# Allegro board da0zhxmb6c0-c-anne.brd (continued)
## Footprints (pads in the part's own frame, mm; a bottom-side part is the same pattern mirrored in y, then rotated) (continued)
BGA1170-INTEL-BRASWELL
  round 0.47 smd: A3(-11.814,-11.951) A52(-11.814,12.383) B2(-11.383,-12.383) B53(-11.383,12.814) BH1(11.383,-12.814) BH53(11.383,12.814) BJ2(11.814,-12.383) BJ52(11.814,12.383) C1(-10.951,-12.814)
  round 0.356 smd: A5(-11.814,-11.17) A6(-11.814,-10.447) A7(-11.814,-9.748) A9(-11.814,-8.836) A47(-11.814,9.621) A48(-11.814,10.294) A49(-11.814,10.992) A51(-11.814,11.773) B4(-11.238,-11.632) B5(-11.222,-11.038) B6(-11.221,-10.445) B8(-11.224,-9.258) B46(-11.224,9.258) B48(-11.221,10.445) B49(-11.222,11.038) B50(-11.238,11.632) B52(-11.225,12.225) BC1(8.621,-12.814) BC2(8.852,-12.246) BC52(8.852,12.246) BC53(8.621,12.814) BD1(9.294,-12.814) BD2(9.445,-12.221) BD52(9.445,12.221) BD53(9.294,12.814) BE1(9.992,-12.814) BE2(10.038,-12.222) BE52(10.038,12.222) BE53(9.992,12.814) BF2(10.632,-12.238) BF52(10.632,12.238) BG1(10.773,-12.814) BG3(10.644,-11.644) BG51(10.644,11.644) BG53(10.773,12.814) BH2(11.225,-12.225) BH4(11.238,-11.632) BH5(11.222,-11.038) BH6(11.221,-10.445) BH8(11.224,-9.258) BH46(11.224,9.258) BH48(11.221,10.445) BH49(11.222,11.038) BH50(11.238,11.632) BH52(11.225,12.225) BJ3(11.814,-11.773) BJ5(11.814,-10.992) BJ6(11.814,-10.294) BJ7(11.814,-9.621) BJ47(11.814,9.621) BJ48(11.814,10.294) BJ49(11.814,10.992) BJ51(11.814,11.773) C3(-10.644,-11.644) C51(-10.644,11.644) C53(-10.773,12.814) D2(-10.632,-12.238) D52(-10.632,12.238) E1(-10.17,-12.814) E2(-10.038,-12.222) E52(-10.038,12.222) E53(-9.992,12.814) F1(-9.447,-12.814) F2(-9.445,-12.221) F52(-9.445,12.221) F53(-9.294,12.814) G1(-8.679,-12.814) G2(-8.852,-12.246) G52(-8.852,12.246) G53(-8.621,12.814) J1(-7.816,-12.814)
  oval 0.343x0.254 smd: A11(-11.814,-7.774) A13(-11.814,-6.803) A15(-11.814,-5.831) A17(-11.814,-4.859) A19(-11.814,-3.887) A21(-11.814,-2.915) A23(-11.814,-1.944) A25(-11.814,-0.972) A27(-11.814,0) A29(-11.814,0.972) A31(-11.814,1.944) A33(-11.814,2.915) A35(-11.814,3.887) A37(-11.814,4.859) A39(-11.814,5.831) A41(-11.814,6.803) A43(-11.814,7.774) A45(-11.814,8.746) BJ9(11.814,-8.746) BJ11(11.814,-7.774) BJ13(11.814,-6.803) BJ15(11.814,-5.831) BJ17(11.814,-4.859) BJ19(11.814,-3.887) BJ21(11.814,-2.915) BJ23(11.814,-1.944) BJ25(11.814,-0.972) BJ27(11.814,0) BJ29(11.814,0.972) BJ31(11.814,1.944) BJ33(11.814,2.915) BJ35(11.814,3.887) BJ37(11.814,4.859) BJ39(11.814,5.831) BJ41(11.814,6.803) BJ43(11.814,7.774) BJ45(11.814,8.746)
  custom 0.064x0.064 smd: AA1(-1.944,-12.814) AA53(-1.944,12.814) AC1(-0.972,-12.814) AC53(-0.972,12.814) AE1(0,-12.814) AE53(0,12.814) AG1(0.972,-12.814) AG53(0.972,12.814) AJ1(1.944,-12.814) AJ53(1.944,12.814) AL1(2.915,-12.814) AL53(2.915,12.814) AN1(3.887,-12.814) AN53(3.887,12.814) AR1(4.859,-12.814) AR53(4.859,12.814) AU1(5.831,-12.814) AU53(5.831,12.814) AW1(6.803,-12.814) AW53(6.803,12.814) BA1(7.774,-12.814) BA53(7.774,12.814) J53(-7.774,12.814) L1(-6.803,-12.814) L53(-6.802,12.814) N1(-5.831,-12.814) N53(-5.831,12.814) R1(-4.859,-12.814) R53(-4.859,12.814) U1(-3.887,-12.814) U53(-3.887,12.814) W1(-2.915,-12.814) W53(-2.915,12.814)
  round 0.279 smd: AA3(-1.944,-12.071) AA51(-1.944,12.071) AB2(-1.458,-12.429) AB3(-1.458,-11.73) AB51(-1.458,11.73) AB52(-1.458,12.429) AC3(-0.972,-12.071) AC51(-0.972,12.071) AD2(-0.486,-12.429) AD3(-0.48,-11.715) AD51(-0.48,11.715) AD52(-0.486,12.429) AE3(0,-12.071) AE4(0,-11.366) AE50(0,11.366) AE51(0,12.071) AF2(0.486,-12.429) AF3(0.48,-11.715) AF51(0.48,11.715) AF52(0.486,12.429) AG3(0.972,-12.071) AG51(0.972,12.071) AH2(1.458,-12.429) AH3(1.458,-11.73) AH51(1.458,11.73) AH52(1.458,12.429) AJ3(1.944,-12.071) AJ51(1.944,12.071) AK2(2.43,-12.429) AK3(2.43,-11.73) AK51(2.43,11.73) AK52(2.43,12.429) AL3(2.915,-12.071) AL51(2.915,12.071) AM2(3.401,-12.429) AM3(3.401,-11.73) AM51(3.401,11.73) AM52(3.401,12.429) AN3(3.887,-12.071) AN51(3.887,12.071) AP2(4.373,-12.429) AP3(4.373,-11.73) AP51(4.373,11.73) AP52(4.373,12.429) AR3(4.859,-12.071) AR51(4.859,12.071) AT2(5.345,-12.429) AT3(5.345,-11.73) AT51(5.345,11.73) AT52(5.345,12.429) AU3(5.831,-12.071) AU51(5.831,12.071) AV2(6.317,-12.429) AV3(6.317,-11.73) AV51(6.317,11.73) AV52(6.317,12.429) AW3(6.803,-12.071) AW51(6.803,12.071) AY2(7.289,-12.429) AY3(7.289,-11.73) AY51(7.289,11.73) AY52(7.289,12.429) B10(-11.429,-8.26) B12(-11.429,-7.289) B14(-11.429,-6.317) B16(-11.429,-5.345) B18(-11.429,-4.373) B20(-11.429,-3.401) B22(-11.429,-2.43) B24(-11.429,-1.458) B26(-11.429,-0.486) B28(-11.429,0.486) B30(-11.429,1.458) B32(-11.429,2.43) B34(-11.429,3.401) B36(-11.429,4.373) B38(-11.429,5.345) B40(-11.429,6.317) B42(-11.429,7.289) B44(-11.429,8.26) BA3(7.774,-12.071) BA51(7.774,12.071) BB3(8.351,-11.929) BB51(8.351,11.929) BF27(10.366,0) BG9(11.028,-8.698) BG11(11.071,-7.774) BG12(10.73,-7.289) BG13(11.071,-6.803) BG14(10.73,-6.317) BG15(11.071,-5.831) BG16(10.73,-5.345) BG17(11.071,-4.859) BG18(10.73,-4.373) BG19(11.071,-3.887) BG20(10.73,-3.401) BG21(11.071,-2.915) BG22(10.73,-2.43) BG23(11.071,-1.944) BG24(10.73,-1.458) BG25(11.071,-0.972) BG26(10.715,-0.48) BG27(11.071,0) BG28(10.715,0.48) BG29(11.071,0.972) BG30(10.73,1.458) BG31(11.071,1.944) BG32(10.73,2.43) BG33(11.071,2.915) BG34(10.73,3.401) BG35(11.071,3.887) BG36(10.73,4.373) BG37(11.071,4.859) BG38(10.73,5.345) BG39(11.071,5.831) BG40(10.73,6.317) BG41(11.071,6.803) BG42(10.73,7.289) BG43(11.071,7.774) BG45(11.028,8.698) BH10(11.429,-8.26) BH12(11.429,-7.289) BH14(11.429,-6.317) BH16(11.429,-5.345) BH18(11.429,-4.373) BH20(11.429,-3.401) BH22(11.429,-2.43) BH24(11.429,-1.458) BH26(11.429,-0.486) BH28(11.429,0.486) BH30(11.429,1.458) BH32(11.429,2.43) BH34(11.429,3.401) BH36(11.429,4.373) BH38(11.429,5.345) BH40(11.429,6.317) BH42(11.429,7.289) BH44(11.429,8.26) C9(-11.028,-8.698) C11(-11.071,-7.774) C12(-10.73,-7.289) C13(-11.071,-6.803) C14(-10.73,-6.317) C15(-11.071,-5.831) C16(-10.73,-5.345) C17(-11.071,-4.859) C18(-10.73,-4.373) C19(-11.071,-3.887) C20(-10.73,-3.401) C21(-11.071,-2.915) C22(-10.73,-2.43) C23(-11.071,-1.944) C24(-10.73,-1.458) C25(-11.071,-0.972) C26(-10.715,-0.48) C27(-11.071,0) C28(-10.715,0.48) C29(-11.071,0.972) C30(-10.73,1.458) C31(-11.071,1.944) C32(-10.73,2.43) C33(-11.071,2.915) C34(-10.73,3.401) C35(-11.071,3.887) C36(-10.73,4.373) C37(-11.071,4.859) C38(-10.73,5.345) C39(-11.071,5.831) C40(-10.73,6.317) C41(-11.071,6.803) C42(-10.73,7.289) C43(-11.071,7.774) C45(-11.028,8.698) D27(-10.366,0) H3(-8.351,-11.929) H51(-8.351,11.929) J3(-7.774,-12.071) J51(-7.774,12.071) K2(-7.289,-12.429) K3(-7.289,-11.73) K51(-7.289,11.73) K52(-7.289,12.429) L3(-6.803,-12.071) L51(-6.803,12.071) M2(-6.317,-12.429) M3(-6.317,-11.73) M51(-6.317,11.73) M52(-6.317,12.429) N3(-5.831,-12.071) N51(-5.831,12.071) P2(-5.345,-12.429) P3(-5.345,-11.73) P51(-5.345,11.73) P52(-5.345,12.429) R3(-4.859,-12.071) R51(-4.859,12.071) T2(-4.373,-12.429) T3(-4.373,-11.73) T51(-4.373,11.73) T52(-4.373,12.429) U3(-3.887,-12.071) U51(-3.887,12.071) V2(-3.401,-12.429) V3(-3.401,-11.73) V51(-3.401,11.73) V52(-3.401,12.429) W3(-2.915,-12.071) W51(-2.915,12.071) Y2(-2.43,-12.429) Y3(-2.43,-11.73) Y51(-2.43,11.73) Y52(-2.43,12.429)
  round 0.33 smd: AA16(-1.961,-5.307) AA18(-1.961,-4.549) AA19(-1.961,-3.791) AA21(-1.961,-3.033) AA22(-1.961,-2.275) AA24(-1.961,-1.516) AA25(-1.961,-0.758) AA27(-1.961,0) AA29(-1.961,0.758) AA30(-1.961,1.516) AA32(-1.961,2.275) AA33(-1.961,3.033) AA35(-1.961,3.791) AA36(-1.961,4.549) AA38(-1.961,5.307) AC16(-1.177,-5.307) AC18(-1.177,-4.549) AC19(-1.177,-3.791) AC21(-1.177,-3.033) AC22(-1.177,-2.275) AC24(-1.177,-1.516) AC25(-1.177,-0.758) AC27(-1.177,0) AC29(-1.177,0.758) AC30(-1.177,1.516) AC32(-1.177,2.275) AC33(-1.177,3.033) AC35(-1.177,3.791) AC36(-1.177,4.549) AC38(-1.177,5.307) AD16(-0.392,-5.307) AD18(-0.392,-4.549) AD19(-0.392,-3.791) AD21(-0.392,-3.033) AD22(-0.392,-2.275) AD24(-0.392,-1.516) AD25(-0.392,-0.758) AD27(-0.392,0) AD29(-0.392,0.758) AD30(-0.392,1.516) AD32(-0.392,2.275) AD33(-0.392,3.033) AD35(-0.392,3.791) AD36(-0.392,4.549) AD38(-0.392,5.307) AF16(0.392,-5.307) AF18(0.392,-4.549) AF19(0.392,-3.791) AF21(0.392,-3.033) AF22(0.392,-2.275) AF24(0.392,-1.516) AF25(0.392,-0.758) AF27(0.392,0) AF29(0.392,0.758) AF30(0.392,1.516) AF32(0.392,2.275) AF33(0.392,3.033) AF35(0.392,3.791) AF36(0.392,4.549) AF38(0.392,5.307) AG16(1.177,-5.307) AG18(1.177,-4.549) AG19(1.177,-3.791) AG21(1.177,-3.033) AG22(1.177,-2.275) AG24(1.177,-1.516) AG25(1.177,-0.758) AG27(1.177,0) AG29(1.177,0.758) AG30(1.177,1.516) AG32(1.177,2.275) AG33(1.177,3.033) AG35(1.177,3.791) AG36(1.177,4.549) AG38(1.177,5.307) AJ16(1.961,-5.307) AJ18(1.961,-4.549) AJ19(1.961,-3.791) AJ21(1.961,-3.033) AJ22(1.961,-2.275) AJ24(1.961,-1.516) AJ25(1.961,-0.758) AJ27(1.961,0) AJ29(1.961,0.758) AJ30(1.961,1.516) AJ32(1.961,2.275) AJ33(1.961,3.033) AJ35(1.961,3.791) AJ36(1.961,4.549) AJ38(1.961,5.307) AK16(2.745,-5.307) AK18(2.745,-4.549) AK19(2.745,-3.791) AK21(2.745,-3.033) AK22(2.745,-2.275) AK24(2.745,-1.516) AK25(2.745,-0.758) AK27(2.745,0) AK29(2.745,0.758) AK30(2.745,1.516) AK32(2.745,2.275) AK33(2.745,3.033) AK35(2.745,3.791) AK36(2.745,4.549) AK38(2.745,5.307) AM16(3.53,-5.307) AM18(3.53,-4.549) AM19(3.53,-3.791) AM21(3.53,-3.033) AM22(3.53,-2.275) AM24(3.53,-1.516) AM25(3.53,-0.758) AM27(3.53,0) AM29(3.53,0.758) AM30(3.53,1.516) AM32(3.53,2.275) AM33(3.53,3.033) AM35(3.53,3.791) AM36(3.53,4.549) AM38(3.53,5.307) AN16(4.314,-5.307) AN18(4.314,-4.549) AN19(4.314,-3.791) AN21(4.314,-3.033) AN22(4.314,-2.275) AN24(4.314,-1.516) AN25(4.314,-0.758) AN27(4.314,0) AN29(4.314,0.758) AN30(4.314,1.516) AN32(4.314,2.275) AN33(4.314,3.033) AN35(4.314,3.791) AN36(4.314,4.549) AN38(4.314,5.307) U16(-4.314,-5.307) U18(-4.314,-4.549) U19(-4.314,-3.791) U21(-4.314,-3.033) U22(-4.314,-2.275) U24(-4.314,-1.516) U25(-4.314,-0.758) U27(-4.314,0) U29(-4.314,0.758) U30(-4.314,1.516) U32(-4.314,2.275) U33(-4.314,3.033) U35(-4.314,3.791) U36(-4.314,4.549) U38(-4.314,5.307) V16(-3.53,-5.307) V18(-3.53,-4.549) V19(-3.53,-3.791) V21(-3.53,-3.033) V22(-3.53,-2.275) V24(-3.53,-1.516) V25(-3.53,-0.758) V27(-3.53,0) V29(-3.53,0.758) V30(-3.53,1.516) V32(-3.53,2.275) V33(-3.53,3.033) V35(-3.53,3.791) V36(-3.53,4.549) V38(-3.53,5.307) Y16(-2.745,-5.307) Y18(-2.745,-4.549) Y19(-2.745,-3.791) Y21(-2.745,-3.033) Y22(-2.745,-2.275) Y24(-2.745,-1.516) Y25(-2.745,-0.758) Y27(-2.745,0) Y29(-2.745,0.758) Y30(-2.745,1.516) Y32(-2.745,2.275) Y33(-2.745,3.033) Y35(-2.745,3.791) Y36(-2.745,4.549) Y38(-2.745,5.307)
  round 0.305 smd: AB4(-1.448,-11.137) AB6(-1.448,-10.463) AB7(-1.448,-9.752) AB9(-1.448,-9.041) AB10(-1.448,-8.33) AB12(-1.448,-7.618) AB13(-1.448,-6.907) AB14(-1.448,-6.196) AB40(-1.448,6.196) AB41(-1.448,6.907) AB42(-1.448,7.618) AB44(-1.448,8.33) AB45(-1.448,9.041) AB47(-1.448,9.752) AB48(-1.448,10.463) AB50(-1.448,11.137) AD4(-0.463,-10.995) AD6(-0.525,-10.404) AD7(-0.475,-9.752) AD9(-0.475,-9.041) AD10(-0.475,-8.33) AD12(-0.475,-7.618) AD13(-0.475,-6.907) AD14(-0.475,-6.196) AD40(-0.475,6.196) AD41(-0.475,6.907) AD42(-0.475,7.618) AD44(-0.475,8.33) AD45(-0.475,9.041) AD47(-0.475,9.752) AD48(-0.525,10.404) AD50(-0.463,10.995) AE6(0,-10.108) AE8(0,-9.396) AE9(0,-8.685) AE11(0,-7.974) AE12(0,-7.263) AE14(0,-6.552) AE40(0,6.552) AE42(0,7.263) AE43(0,7.974) AE45(0,8.685) AE46(0,9.396) AE48(0,10.108) AF4(0.463,-10.995) AF6(0.525,-10.404) AF7(0.475,-9.752) AF9(0.475,-9.041) AF10(0.475,-8.33) AF12(0.475,-7.618) AF13(0.475,-6.907) AF14(0.475,-6.196) AF40(0.475,6.196) AF41(0.475,6.907) AF42(0.475,7.618) AF44(0.475,8.33) AF45(0.475,9.041) AF47(0.475,9.752) AF48(0.525,10.404) AF50(0.463,10.995) AH4(1.448,-11.137) AH6(1.448,-10.463) AH7(1.448,-9.752) AH9(1.448,-9.041) AH10(1.448,-8.33) AH12(1.448,-7.618) AH13(1.448,-6.907) AH14(1.448,-6.196) AH40(1.448,6.196) AH41(1.448,6.907) AH42(1.448,7.618) AH44(1.448,8.33) AH45(1.448,9.041) AH47(1.448,9.752) AH48(1.448,10.463) AH50(1.448,11.137) AK4(2.439,-11.137) AK6(2.439,-10.463) AK7(2.439,-9.752) AK9(2.439,-9.041) AK10(2.439,-8.33) AK12(2.439,-7.618) AK13(2.439,-6.907) AK14(2.439,-6.196) AK40(2.439,6.196) AK41(2.439,6.907) AK42(2.439,7.618) AK44(2.439,8.33) AK45(2.439,9.041) AK47(2.439,9.752) AK48(2.439,10.463) AK50(2.439,11.137) AM4(3.386,-11.137) AM6(3.412,-10.463) AM7(3.412,-9.752) AM9(3.412,-9.041) AM10(3.412,-8.33) AM12(3.412,-7.618) AM13(3.412,-6.907) AM14(3.412,-6.196) AM40(3.412,6.196) AM41(3.412,6.907) AM42(3.412,7.618) AM44(3.412,8.33) AM45(3.412,9.041) AM47(3.412,9.752) AM48(3.412,10.463) AM50(3.386,11.137) AN5(3.887,-10.819) AN6(3.887,-10.108) AN8(3.887,-9.396) AN9(3.887,-8.685) AN11(3.887,-7.974) AN12(3.887,-7.263) AN14(3.887,-6.552) AN40(3.887,6.552) AN42(3.887,7.263) AN43(3.887,7.974) AN45(3.887,8.685) AN46(3.887,9.396) AN48(3.887,10.108) AN49(3.887,10.819) AP4(4.388,-11.137) AP6(4.362,-10.463) AP7(4.362,-9.752) AP9(4.362,-9.041) AP10(4.362,-8.33) AP12(4.362,-7.618) AP13(4.362,-6.907) AP14(4.362,-6.196) AP40(4.362,6.196) AP41(4.362,6.907) AP42(4.362,7.618) AP44(4.362,8.33) AP45(4.362,9.041) AP47(4.362,9.752) AP48(4.362,10.463) AP50(4.388,11.137) AT4(5.336,-11.137) AT6(5.336,-10.463) AT7(5.336,-9.752) AT9(5.336,-9.041) AT10(5.336,-8.33) AT12(5.336,-7.618) AT13(5.336,-6.907) AT14(5.336,-6.305) AT16(5.196,-5.336) AT18(5.196,-4.362) AT19(5.552,-3.887) AT20(5.196,-3.412) AT22(5.196,-2.439) AT24(5.196,-1.448) AT26(5.196,-0.475) AT27(5.552,0) AT28(5.196,0.475) AT30(5.196,1.448) AT32(5.196,2.439) AT34(5.196,3.412) AT35(5.552,3.887) AT36(5.196,4.362) AT38(5.196,5.336) AT40(5.336,6.305) AT41(5.336,6.907) AT42(5.336,7.618) AT44(5.336,8.33) AT45(5.336,9.041) AT47(5.336,9.752) AT48(5.336,10.463) AT50(5.336,11.137) AU16(5.907,-5.336) AU18(5.907,-4.362) AU20(5.907,-3.412) AU22(5.907,-2.439) AU24(5.907,-1.448) AU26(5.907,-0.475) AU28(5.907,0.475) AU30(5.907,1.448) AU32(5.907,2.439) AU34(5.907,3.412) AU36(5.907,4.362) AU38(5.907,5.336) AV4(6.326,-11.137) AV6(6.326,-10.463) AV7(6.326,-9.752) AV9(6.326,-9.041) AV10(6.326,-8.33) AV12(6.326,-7.618) AV13(6.326,-6.907) AV14(6.446,-6.326) AV16(6.618,-5.336) AV18(6.618,-4.362) AV19(6.263,-3.887) AV20(6.618,-3.412) AV22(6.618,-2.439) AV24(6.618,-1.448) AV26(6.618,-0.475) AV27(6.263,0) AV28(6.618,0.475) AV30(6.618,1.448) AV32(6.618,2.439) AV34(6.618,3.412) AV35(6.263,3.887) AV36(6.618,4.362) AV38(6.618,5.336) AV40(6.446,6.326) AV41(6.326,6.907) AV42(6.326,7.618) AV44(6.326,8.33) AV45(6.326,9.041) AV47(6.326,9.752) AV48(6.326,10.463) AV50(6.326,11.137) AW13(6.915,-6.751) AW19(6.974,-3.887) AW27(6.974,0) AW35(6.974,3.887) AW41(6.915,6.751) AY4(7.317,-11.137) AY6(7.317,-10.463) AY7(7.317,-9.752) AY9(7.317,-9.041) AY10(7.317,-8.33) AY12(7.34,-7.317) AY14(7.33,-6.326) AY16(7.33,-5.336) AY18(7.33,-4.362) AY20(7.33,-3.412) AY22(7.33,-2.439) AY24(7.33,-1.448) AY26(7.33,-0.475) AY28(7.33,0.475) AY30(7.33,1.448) AY32(7.33,2.439) AY34(7.33,3.412) AY36(7.33,4.362) AY38(7.33,5.336) AY40(7.33,6.326) AY42(7.34,7.317) AY44(7.317,8.33) AY45(7.317,9.041) AY47(7.317,9.752) AY48(7.317,10.463) AY50(7.317,11.137) B7(-11.23,-9.852) B47(-11.23,9.852) BA12(8.041,-7.317) BA14(8.041,-6.326) BA16(8.041,-5.336) BA18(8.041,-4.362) BA19(7.685,-3.887) BA20(8.041,-3.412) BA22(8.041,-2.439) BA24(8.041,-1.448) BA26(8.041,-0.475) BA27(7.685,0) BA28(8.041,0.475) BA30(8.041,1.448) BA32(8.041,2.439) BA34(8.041,3.412) BA35(7.685,3.887) BA36(8.041,4.362) BA38(8.041,5.336) BA40(8.041,6.326) BA42(8.041,7.317) BB4(8.307,-11.258) BB5(8.307,-10.547) BB7(8.307,-9.835) BB8(8.307,-9.124) BB10(8.17,-8.307) BB19(8.396,-3.887) BB27(8.396,0) BB35(8.396,3.887) BB44(8.17,8.307) BB46(8.307,9.124) BB47(8.307,9.835) BB49(8.307,10.547) BB50(8.307,11.258) BC10(8.764,-8.307) BC12(8.752,-7.317) BC14(8.752,-6.326) BC16(8.752,-5.336) BC18(8.752,-4.362) BC20(8.752,-3.412) BC22(8.752,-2.439) BC24(8.752,-1.448) BC26(8.752,-0.475) BC28(8.752,0.475) BC30(8.752,1.448) BC32(8.752,2.439) BC34(8.752,3.412) BC36(8.752,4.362) BC38(8.752,5.336) BC40(8.752,6.326) BC42(8.752,7.317) BC44(8.764,8.307) BD5(9.302,-10.565) BD7(9.302,-9.712) BD10(9.457,-8.307) BD12(9.463,-7.317) BD14(9.463,-6.326) BD16(9.463,-5.336) BD18(9.463,-4.362) BD19(9.108,-3.887) BD20(9.463,-3.412) BD22(9.463,-2.439) BD24(9.463,-1.448) BD26(9.404,-0.525) BD27(9.108,0) BD28(9.404,0.525) BD30(9.463,1.448) BD32(9.463,2.439) BD34(9.463,3.412) BD35(9.108,3.887) BD36(9.463,4.362) BD38(9.463,5.336) BD40(9.463,6.326) BD42(9.463,7.317) BD44(9.457,8.307) BD47(9.302,9.712) BD49(9.302,10.565) BE3(9.58,-11.643) BE8(9.747,-9.32) BE19(9.819,-3.887) BE35(9.819,3.887) BE46(9.747,9.32) BE51(9.58,11.643) BF4(10.163,-11.163) BF6(10.238,-10.113) BF10(10.168,-8.307) BF12(10.137,-7.317) BF14(10.137,-6.326) BF16(10.137,-5.336) BF18(10.137,-4.388) BF20(10.137,-3.386) BF22(10.137,-2.439) BF24(10.137,-1.448) BF26(9.995,-0.463) BF28(9.995,0.463) BF30(10.137,1.448) BF32(10.137,2.439) BF34(10.137,3.386) BF36(10.137,4.388) BF38(10.137,5.336) BF40(10.137,6.326) BF42(10.137,7.317) BF44(10.168,8.307) BF48(10.238,10.113) BF50(10.163,11.163) BG5(10.643,-10.58) BG7(10.709,-9.553) BG47(10.709,9.553) BG49(10.643,10.58) BH7(11.23,-9.852) BH47(11.23,9.852) C5(-10.643,-10.58) C7(-10.709,-9.553) C47(-10.709,9.553) C49(-10.643,10.58) D4(-10.163,-11.163) D6(-10.238,-10.113) D10(-10.168,-8.307) D12(-10.137,-7.317) D14(-10.137,-6.326) D16(-10.137,-5.336) D18(-10.137,-4.388) D20(-10.137,-3.386) D22(-10.137,-2.439) D24(-10.137,-1.448) D26(-9.995,-0.463) D28(-9.995,0.463) D30(-10.137,1.448) D32(-10.137,2.439) D34(-10.137,3.386) D36(-10.137,4.388) D38(-10.137,5.336) D40(-10.137,6.326) D42(-10.137,7.317) D44(-10.168,8.307) D48(-10.238,10.113) D50(-10.163,11.163) E3(-9.58,-11.643) E8(-9.747,-9.32) E19(-9.819,-3.887) E35(-9.819,3.887) E46(-9.747,9.32) E51(-9.58,11.643) F5(-9.302,-10.565) F7(-9.302,-9.712) F10(-9.457,-8.307) F12(-9.463,-7.317) F14(-9.463,-6.326) F16(-9.463,-5.336) F18(-9.463,-4.362) F19(-9.108,-3.887) F20(-9.463,-3.412) F22(-9.463,-2.439) F24(-9.463,-1.448) F26(-9.404,-0.525) F27(-9.108,0) F28(-9.404,0.525) F30(-9.463,1.448) F32(-9.463,2.439) F34(-9.463,3.412) F35(-9.108,3.887) F36(-9.463,4.362) F38(-9.463,5.336) F40(-9.463,6.326) F42(-9.463,7.317) F44(-9.457,8.307) F47(-9.302,9.712) F49(-9.302,10.565) G10(-8.764,-8.307) G12(-8.752,-7.317) G14(-8.752,-6.326) G16(-8.752,-5.336) G18(-8.752,-4.362) G20(-8.752,-3.412) G22(-8.752,-2.439) G24(-8.752,-1.448) G26(-8.752,-0.475) G28(-8.752,0.475) G30(-8.752,1.448) G32(-8.752,2.439) G34(-8.752,3.412) G36(-8.752,4.362) G38(-8.752,5.336) G40(-8.752,6.326) G42(-8.752,7.317) G44(-8.764,8.307) H4(-8.307,-11.258) H5(-8.307,-10.547) H7(-8.307,-9.835) H8(-8.307,-9.124) H10(-8.17,-8.307) H19(-8.396,-3.887) H27(-8.396,0) H35(-8.396,3.887) H44(-8.17,8.307) H46(-8.307,9.124) H47(-8.307,9.835) H49(-8.307,10.547) H50(-8.307,11.258) J12(-8.041,-7.317) J14(-8.041,-6.326) J16(-8.041,-5.336) J18(-8.041,-4.362) J19(-7.685,-3.887) J20(-8.041,-3.412) J22(-8.041,-2.439) J24(-8.041,-1.448) J26(-8.041,-0.475) J27(-7.685,0) J28(-8.041,0.475) J30(-8.041,1.448) J32(-8.041,2.439) J34(-8.041,3.412) J35(-7.685,3.887) J36(-8.041,4.362) J38(-8.041,5.336) J40(-8.041,6.326) J42(-8.041,7.317) K4(-7.317,-11.137) K6(-7.317,-10.463) K7(-7.317,-9.752) K9(-7.317,-9.041) K10(-7.317,-8.33) K12(-7.34,-7.317) K14(-7.33,-6.326) K16(-7.33,-5.336) K18(-7.33,-4.362) K20(-7.33,-3.412) K22(-7.33,-2.439) K24(-7.33,-1.448) K26(-7.33,-0.475) K28(-7.33,0.475) K30(-7.33,1.448) K32(-7.33,2.439) K34(-7.33,3.412) K36(-7.33,4.362) K38(-7.33,5.336) K40(-7.33,6.326) K42(-7.34,7.317) K44(-7.317,8.33) K45(-7.317,9.041) K47(-7.317,9.752) K48(-7.317,10.463) K50(-7.317,11.137) L13(-6.915,-6.751) L19(-6.974,-3.887) L27(-6.974,0) L35(-6.974,3.887) L41(-6.915,6.751) M4(-6.326,-11.137) M6(-6.326,-10.463) M7(-6.326,-9.752) M9(-6.326,-9.041) M10(-6.326,-8.33) M12(-6.326,-7.618) M13(-6.326,-6.907) M14(-6.446,-6.326) M16(-6.618,-5.336) M18(-6.618,-4.362) M19(-6.263,-3.887) M20(-6.618,-3.412) M22(-6.618,-2.439) M24(-6.618,-1.448) M26(-6.618,-0.475) M27(-6.263,0) M28(-6.618,0.475) M30(-6.618,1.448) M32(-6.618,2.439) M34(-6.618,3.412) M35(-6.263,3.887) M36(-6.618,4.362) M38(-6.618,5.336) M40(-6.446,6.326) M41(-6.326,6.907) M42(-6.326,7.618) M44(-6.326,8.33) M45(-6.326,9.041) M47(-6.326,9.752) M48(-6.326,10.463) M50(-6.326,11.137) N16(-5.907,-5.336) N18(-5.907,-4.362) N20(-5.907,-3.412) N22(-5.907,-2.439) N24(-5.907,-1.448) N26(-5.907,-0.475) N28(-5.907,0.475) N30(-5.907,1.448) N32(-5.907,2.439) N34(-5.907,3.412) N36(-5.907,4.362) N38(-5.907,5.336) P4(-5.336,-11.137) P6(-5.336,-10.463) P7(-5.336,-9.752) P9(-5.336,-9.041) P10(-5.336,-8.33) P12(-5.336,-7.618) P13(-5.336,-6.907) P14(-5.336,-6.305) P16(-5.196,-5.336) P18(-5.196,-4.362) P19(-5.552,-3.887) P20(-5.196,-3.412) P22(-5.196,-2.439) P24(-5.196,-1.448) P26(-5.196,-0.475) P27(-5.552,0) P28(-5.196,0.475) P30(-5.196,1.448) P32(-5.196,2.439) P34(-5.196,3.412) P35(-5.552,3.887) P36(-5.196,4.362) P38(-5.196,5.336) P40(-5.336,6.305) P41(-5.336,6.907) P42(-5.336,7.618) P44(-5.336,8.33) P45(-5.336,9.041) P47(-5.336,9.752) P48(-5.336,10.463) P50(-5.336,11.137) T4(-4.388,-11.137) T6(-4.362,-10.463) T7(-4.362,-9.752) T9(-4.362,-9.041) T10(-4.362,-8.33) T12(-4.362,-7.618) T13(-4.362,-6.907) T14(-4.362,-6.196) T40(-4.362,6.196) T41(-4.362,6.907) T42(-4.362,7.618) T44(-4.362,8.33) T45(-4.362,9.041) T47(-4.362,9.752) T48(-4.362,10.463) T50(-4.388,11.137) U5(-3.887,-10.819) U6(-3.887,-10.108) U8(-3.887,-9.396) U9(-3.887,-8.685) U11(-3.887,-7.974) U12(-3.887,-7.263) U14(-3.887,-6.552) U40(-3.887,6.552) U42(-3.887,7.263) U43(-3.887,7.974) U45(-3.887,8.685) U46(-3.887,9.396) U48(-3.887,10.108) U49(-3.887,10.819) V4(-3.386,-11.137) V6(-3.412,-10.463) V7(-3.412,-9.752) V9(-3.412,-9.041) V10(-3.412,-8.33) V12(-3.412,-7.618) V13(-3.412,-6.907) V14(-3.412,-6.196) V40(-3.412,6.196) V41(-3.412,6.907) V42(-3.412,7.618) V44(-3.412,8.33) V45(-3.412,9.041) V47(-3.412,9.752) V48(-3.412,10.463) V50(-3.386,11.137) Y4(-2.439,-11.137) Y6(-2.439,-10.463) Y7(-2.439,-9.752) Y9(-2.439,-9.041) Y10(-2.439,-8.33) Y12(-2.439,-7.618) Y13(-2.439,-6.907) Y14(-2.439,-6.196) Y40(-2.439,6.196) Y41(-2.439,6.907) Y42(-2.439,7.618) Y44(-2.439,8.33) Y45(-2.439,9.041) Y47(-2.439,9.752) Y48(-2.439,10.463) Y50(-2.439,11.137)
C0201
  rect 0.203x0.381 smd: 1(-0.225,0) 2(0.225,0)
C0402
  custom 0.12x0.12 smd: 1(0.39,0) 2(-0.39,0)
C0603
  rect 0.813x0.813 smd: 1(0.6,0) 2(-0.6,0)
C0805
  rect 0.864x1.372 smd: 1(0.88,0) 2(-0.88,0)
C1206
  rect 1.219x1.626 smd: 1(1.4,0) 2(-1.4,0)
C3528
  rect 1.6x2.591 smd: 1(1.5,0) 2(-1.5,0)
CC7343
  rect 2.413x2.819 smd: 1(-3.2,0) 2(3.2,0)
CHOKE-PCMC063T-3R3MN-SMT
  rect 1.854x3.505 smd: 1(-3.275,0) 2(3.275,0)
CHOKE-PCMC063T-R82MN-4P-SMT
  custom 0.591x0.591 smd: 1(-3.596,0) 2(3.596,0)
  rect 1.473x0.305 smd: 3(-2.452,0) 4(2.452,0)
D-DO-214AC
  rect 1.88x2.032 smd: 1(-2.1,0) 2(2.1,0)
D-TO277_213-6_1X4_3
  rect 1.168x1.397 smd: 1(3.885,1.05) 2(3.885,-1.05)
  rect 4.648x3.505 smd: 3(0,0)
DCJK-2DC3079-007111F-2P
  oval 1.295x2.591 hole 0.711x2.007: 1(4.65,5.6) 3(4.65,0) 4(-4.65,0)
  oval 1.702x2.794 hole 1.092x2.21: 2(-4.65,5.6)
DSM
  rect 1.016x0.508 smd: 1(-1.3,0) 2(1.321,0)
DSMV
  rect 1.016x0.762 smd: 1(-1.27,0) 2(1.27,0)
FBGA153-SAMSUNG-KLMBG4GEAC
  round 0.305 smd: A1(-3.25,3.25) A2(-2.75,3.25) A3(-2.25,3.25) A4(-1.75,3.25) A5(-1.25,3.25) A6(-0.75,3.25) A7(-0.25,3.25) A8(0.25,3.25) A9(0.75,3.25) A10(1.25,3.25) A11(1.75,3.25) A12(2.25,3.25) A13(2.75,3.25) A14(3.25,3.25) B1(-3.25,2.75) B2(-2.75,2.75) B3(-2.25,2.75) B4(-1.75,2.75) B5(-1.25,2.75) B6(-0.75,2.75) B7(-0.25,2.75) B8(0.25,2.75) B9(0.75,2.75) B10(1.25,2.75) B11(1.75,2.75) B12(2.25,2.75) B13(2.75,2.75) B14(3.25,2.75) C1(-3.25,2.25) C2(-2.75,2.25) C3(-2.25,2.25) C4(-1.75,2.25) C5(-1.25,2.25) C6(-0.75,2.25) C7(-0.25,2.25) C8(0.25,2.25) C9(0.75,2.25) C10(1.25,2.25) C11(1.75,2.25) C12(2.25,2.25) C13(2.75,2.25) C14(3.25,2.25) D1(-3.25,1.75) D2(-2.75,1.75) D3(-2.25,1.75) D4(-1.75,1.75) D12(2.25,1.75) D13(2.75,1.75) D14(3.25,1.75) E1(-3.25,1.25) E2(-2.75,1.25) E3(-2.25,1.25) E5(-1.25,1.25) E6(-0.75,1.25) E7(-0.25,1.25) E8(0.25,1.25) E9(0.75,1.25) E10(1.25,1.25) E12(2.25,1.25) E13(2.75,1.25) E14(3.25,1.25) F1(-3.25,0.75) F2(-2.75,0.75) F3(-2.25,0.75) F5(-1.25,0.75) F10(1.25,0.75) F12(2.25,0.75) F13(2.75,0.75) F14(3.25,0.75) G1(-3.25,0.25) G2(-2.75,0.25) G3(-2.25,0.25) G5(-1.25,0.25) G10(1.25,0.25) G12(2.25,0.25) G13(2.75,0.25) G14(3.25,0.25) H1(-3.25,-0.25) H2(-2.75,-0.25) H3(-2.25,-0.25) H5(-1.25,-0.25) H10(1.25,-0.25) H12(2.25,-0.25) H13(2.75,-0.25) H14(3.25,-0.25) J1(-3.25,-0.75) J2(-2.75,-0.75) J3(-2.25,-0.75) J5(-1.25,-0.75) J10(1.25,-0.75) J12(2.25,-0.75) J13(2.75,-0.75) J14(3.25,-0.75) K1(-3.25,-1.25) K2(-2.75,-1.25) K3(-2.25,-1.25) K5(-1.25,-1.25) K6(-0.75,-1.25) K7(-0.25,-1.25) K8(0.25,-1.25) K9(0.75,-1.25) K10(1.25,-1.25) K12(2.25,-1.25) K13(2.75,-1.25) K14(3.25,-1.25) L1(-3.25,-1.75) L2(-2.75,-1.75) L3(-2.25,-1.75) L12(2.25,-1.75) L13(2.75,-1.75) L14(3.25,-1.75) M1(-3.25,-2.25) M2(-2.75,-2.25) M3(-2.25,-2.25) M4(-1.75,-2.25) M5(-1.25,-2.25) M6(-0.75,-2.25) M7(-0.25,-2.25) M8(0.25,-2.25) M9(0.75,-2.25) M10(1.25,-2.25) M11(1.75,-2.25) M12(2.25,-2.25) M13(2.75,-2.25) M14(3.25,-2.25) N1(-3.25,-2.75) N2(-2.75,-2.75) N3(-2.25,-2.75) N4(-1.75,-2.75) N5(-1.25,-2.75) N6(-0.75,-2.75) N7(-0.25,-2.75) N8(0.25,-2.75) N9(0.75,-2.75) N10(1.25,-2.75) N11(1.75,-2.75) N12(2.25,-2.75) N13(2.75,-2.75) N14(3.25,-2.75) P1(-3.25,-3.25) P2(-2.75,-3.25) P3(-2.25,-3.25) P4(-1.75,-3.25) P5(-1.25,-3.25) P6(-0.75,-3.25) P7(-0.25,-3.25) P8(0.25,-3.25) P9(0.75,-3.25) P10(1.25,-3.25) P11(1.75,-3.25) P12(2.25,-3.25) P13(2.75,-3.25) P14(3.25,-3.25)
H-C118D118N
  round 2.997 hole 2.997 unplated: (0,0)
H-C142X118D142X118N
  oval 3.607x2.997 hole 3.607x2.997 unplated: (0,0)
H-C276D110P2
  round 7.01 hole 2.794: 1(0,0)
H-O158X118D158X118N
  oval 4.013x2.997 hole 4.013x2.997 unplated: (0,0)
H-TC276IC197BC315D142X134P2
  round 7.01 hole 3.607x3.404: 1(0,0)
H-TC276IC276BC315D110P2
  round 7.01 hole 2.794: 1(0,0)
H-ZHX-1
  round 7.01 hole 3.404: 1(0,0)
H-ZXX-1
  round 5.994 hole 3.988: 1(0,0)
H-ZXX-2
  round 7.01 hole 3.404: 1(0,0)
H-ZXX-6
  custom 2x2 hole 2.794: 1(0,0)
H-ZXX-13
  round 5.994 hole 3.988: 1(0,0)
HDMI-80103-1121-19P-LDV-SMT
  round 0.762 hole 0.559: 1(-4.5,6.08) 2(-4,7.58) 3(-3.5,6.08) 4(-3,7.58) 5(-2.5,6.08) 6(-2,7.58) 7(-1.5,6.08) 8(-1,7.58) 9(-0.5,6.08) 10(0,7.58) 11(0.5,6.08) 12(1,7.58) 13(1.5,6.08) 14(2,7.58) 15(2.5,6.08) 16(3,7.58) 17(3.5,6.08) 18(4,7.58) 19(4.5,6.08)
  oval 1.397x3.15 hole 0.787x2.54: 20(-7.25,6.98) 21(7.25,6.98)
  rect 1.549x2.388 smd: 22(-8.625,0) 23(8.625,0)
IMD
  rect 1.016x0.813 smd: 1(1.2,-1) 3(1.2,1) 4(-1.2,1) 6(-1.2,-1)
  rect 1.016x0.61 smd: 2(1.2,0) 5(-1.2,0)
LEDLTST-S326KGJRKT-3P-SMT
  rect 0.991x0.991 smd: 1(-1.5,0) 3(1.5,0)
  rect 0.889x0.889 smd: 2(0,-0.65)
LGA16-3X3-5
  rect 0.94x0.305 smd: 1(-1.525,1) 2(-1.525,0.5) 3(-1.525,0) 4(-1.525,-0.5) 5(-1.525,-1) 9(1.525,-1) 10(1.525,-0.5) 11(1.525,0) 12(1.525,0.5) 13(1.525,1)
  rect 0.305x0.94 smd: 6(-0.5,-1.525) 7(0,-1.525) 8(0.5,-1.525) 14(0.5,1.525) 15(0,1.525) 16(-0.5,1.525)
LQFP128-16X16-4-1_6H
  rect 0.203x1.499 smd: 1(-6.2,-7.85) 2(-5.8,-7.85) 3(-5.4,-7.85) 4(-5,-7.85) 5(-4.6,-7.85) 6(-4.2,-7.85) 7(-3.8,-7.85) 8(-3.4,-7.85) 9(-3,-7.85) 10(-2.6,-7.85) 11(-2.2,-7.85) 12(-1.8,-7.85) 13(-1.4,-7.85) 14(-1,-7.85) 15(-0.6,-7.85) 16(-0.2,-7.85) 17(0.2,-7.85) 18(0.6,-7.85) 19(1,-7.85) 20(1.4,-7.85) 21(1.8,-7.85) 22(2.2,-7.85) 23(2.6,-7.85) 24(3,-7.85) 25(3.4,-7.85) 26(3.8,-7.85) 27(4.2,-7.85) 28(4.6,-7.85) 29(5,-7.85) 30(5.4,-7.85) 31(5.8,-7.85) 32(6.2,-7.85) 65(6.2,7.85) 66(5.8,7.85) 67(5.4,7.85) 68(5,7.85) 69(4.6,7.85) 70(4.2,7.85) 71(3.8,7.85) 72(3.4,7.85) 73(3,7.85) 74(2.6,7.85) 75(2.2,7.85) 76(1.8,7.85) 77(1.4,7.85) 78(1,7.85) 79(0.6,7.85) 80(0.2,7.85) 81(-0.2,7.85) 82(-0.6,7.85) 83(-1,7.85) 84(-1.4,7.85) 85(-1.8,7.85) 86(-2.2,7.85) 87(-2.6,7.85) 88(-3,7.85) 89(-3.4,7.85) 90(-3.8,7.85) 91(-4.2,7.85) 92(-4.6,7.85) 93(-5,7.85) 94(-5.4,7.85) 95(-5.8,7.85) 96(-6.2,7.85)
  rect 1.499x0.203 smd: 33(7.85,-6.2) 34(7.85,-5.8) 35(7.85,-5.4) 36(7.85,-5) 37(7.85,-4.6) 38(7.85,-4.2) 39(7.85,-3.8) 40(7.85,-3.4) 41(7.85,-3) 42(7.85,-2.6) 43(7.85,-2.2) 44(7.85,-1.8) 45(7.85,-1.4) 46(7.85,-1) 47(7.85,-0.6) 48(7.85,-0.2) 49(7.85,0.2) 50(7.85,0.6) 51(7.85,1) 52(7.85,1.4) 53(7.85,1.8) 54(7.85,2.2) 55(7.85,2.6) 56(7.85,3) 57(7.85,3.4) 58(7.85,3.8) 59(7.85,4.2) 60(7.85,4.6) 61(7.85,5) 62(7.85,5.4) 63(7.85,5.8) 64(7.85,6.2) 97(-7.85,6.2) 98(-7.85,5.8) 99(-7.85,5.4) 100(-7.85,5) 101(-7.85,4.6) 102(-7.85,4.2) 103(-7.85,3.8) 104(-7.85,3.4) 105(-7.85,3) 106(-7.85,2.6) 107(-7.85,2.2) 108(-7.85,1.8) 109(-7.85,1.4) 110(-7.85,1) 111(-7.85,0.6) 112(-7.85,0.2) 113(-7.85,-0.2) 114(-7.85,-0.6) 115(-7.85,-1) 116(-7.85,-1.4) 117(-7.85,-1.8) 118(-7.85,-2.2) 119(-7.85,-2.6) 120(-7.85,-3) 121(-7.85,-3.4) 122(-7.85,-3.8) 123(-7.85,-4.2) 124(-7.85,-4.6) 125(-7.85,-5) 126(-7.85,-5.4) 127(-7.85,-5.8) 128(-7.85,-6.2)
LVDS-107K40-100011-G2-40P-L
  round 1.092 hole 1.092 unplated: (-12.05,0) (12.05,0)
  rect 0.254x1.295 smd: 1(-9.75,1.95) 2(-9.25,1.95) 3(-8.75,1.95) 4(-8.25,1.95) 5(-7.75,1.95) 6(-7.25,1.95) 7(-6.75,1.95) 8(-6.25,1.95) 9(-5.75,1.95) 10(-5.25,1.95) 11(-4.75,1.95) 12(-4.25,1.95) 13(-3.75,1.95) 14(-3.25,1.95) 15(-2.75,1.95) 16(-2.25,1.95) 17(-1.75,1.95) 18(-1.25,1.95) 19(-0.75,1.95) 20(-0.25,1.95) 21(0.25,1.95) 22(0.75,1.95) 23(1.25,1.95) 24(1.75,1.95) 25(2.25,1.95) 26(2.75,1.95) 27(3.25,1.95) 28(3.75,1.95) 29(4.25,1.95) 30(4.75,1.95) 31(5.25,1.95) 32(5.75,1.95) 33(6.25,1.95) 34(6.75,1.95) 35(7.25,1.95) 36(7.75,1.95) 37(8.25,1.95) 38(8.75,1.95) 39(9.25,1.95) 40(9.75,1.95)
  rect 1.549x3.404 smd: 41(-13.875,-3.9) 42(13.875,-3.9)
ML1220-SMT
  round 1.092 hole 1.092 unplated: (0,3.988)
  round 0.711 hole 0.711 unplated: (0,-3.988)
  rect 2.997x1.499 smd: 1(-7.391,0) 2(7.391,0)
MSOP8-4_9-65
  rect 0.406x1.448 smd: 1(-0.975,-2.325) 2(-0.325,-2.325) 3(0.325,-2.325) 4(0.975,-2.325) 5(0.975,2.325) 6(0.325,2.325) 7(-0.325,2.325) 8(-0.975,2.325)
NGFF-51749-0750P-105-75P-KE
  round 1.092 hole 1.092 unplated: (-11,0)
  round 1.6 hole 1.6 unplated: (11,0)
  rect 0.305x1.499 smd: 1(-9.25,1.7) 3(-8.75,1.7) 5(-8.25,1.7) 7(-7.75,1.7) 9(-7.25,1.7) 11(-6.75,1.7) 13(-6.25,1.7) 15(-5.75,1.7) 17(-5.25,1.7) 19(-4.75,1.7) 21(-4.25,1.7) 23(-3.75,1.7) 33(-1.25,1.7) 35(-0.75,1.7) 37(-0.25,1.7) 39(0.25,1.7) 41(0.75,1.7) 43(1.25,1.7) 45(1.75,1.7) 47(2.25,1.7) 49(2.75,1.7) 51(3.25,1.7) 53(3.75,1.7) 55(4.25,1.7) 57(4.75,1.7) 59(5.25,1.7) 61(5.75,1.7) 63(6.25,1.7) 65(6.75,1.7) 67(7.25,1.7) 69(7.75,1.7) 71(8.25,1.7) 73(8.75,1.7) 75(9.25,1.7)
  round 0.762 hole 0.508: 2(-9,-0.89) 4(-8.5,-0.09) 6(-8,-0.89) 8(-7.5,-0.09) 10(-7,-0.89) 12(-6.5,-0.09) 14(-6,-0.89) 16(-5.5,-0.09) 18(-5,-0.89) 20(-4.5,-0.09) 22(-4,-0.89) 32(-1.5,-0.09) 34(-1,-0.89) 36(-0.5,-0.09) 38(0,-0.89) 40(0.5,-0.09) 42(1,-0.89) 44(1.5,-0.09) 46(2,-0.89) 48(2.5,-0.09) 50(3,-0.89) 52(3.5,-0.09) 54(4,-0.89) 56(4.5,-0.09) 58(5,-0.89) 60(5.5,-0.09) 62(6,-0.89) 64(6.5,-0.09) 66(7,-0.89) 68(7.5,-0.09) 70(8,-0.89) 72(8.5,-0.09) 74(9,-0.89)
  oval 0.889x1.956 hole 0.508x1.753: 76(-11.25,-4.05) 77(11.25,-4.05)
NGFF-APCI0018-P002A-75P-KB-SMT
  round 1.194 hole 1.194 unplated: (-10,0)
  round 1.702 hole 1.702 unplated: (10,0)
  rect 0.305x1.549 smd: 1(-9.25,5.275) 2(-9,-2.275) 3(-8.75,5.275) 4(-8.5,-2.275) 5(-8.25,5.275) 6(-8,-2.275) 7(-7.75,5.275) 8(-7.5,-2.275) 9(-7.25,5.275) 10(-7,-2.275) 11(-6.75,5.275) 20(-4.5,-2.275) 21(-4.25,5.275) 22(-4,-2.275) 23(-3.75,5.275) 24(-3.5,-2.275) 25(-3.25,5.275) 26(-3,-2.275) 27(-2.75,5.275) 28(-2.5,-2.275) 29(-2.25,5.275) 30(-2,-2.275) 31(-1.75,5.275) 32(-1.5,-2.275) 33(-1.25,5.275) 34(-1,-2.275) 35(-0.75,5.275) 36(-0.5,-2.275) 37(-0.25,5.275) 38(0,-2.275) 39(0.25,5.275) 40(0.5,-2.275) 41(0.75,5.275) 42(1,-2.275) 43(1.25,5.275) 44(1.5,-2.275) 45(1.75,5.275) 46(2,-2.275) 47(2.25,5.275) 48(2.5,-2.275) 49(2.75,5.275) 50(3,-2.275) 51(3.25,5.275) 52(3.5,-2.275) 53(3.75,5.275) 54(4,-2.275) 55(4.25,5.275) 56(4.5,-2.275) 57(4.75,5.275) 58(5,-2.275) 59(5.25,5.275) 60(5.5,-2.275) 61(5.75,5.275) 62(6,-2.275) 63(6.25,5.275) 64(6.5,-2.275) 65(6.75,5.275) 66(7,-2.275) 67(7.25,5.275) 68(7.5,-2.275) 69(7.75,5.275) 70(8,-2.275) 71(8.25,5.275) 72(8.5,-2.275) 73(8.75,5.275) 74(9,-2.275) 75(9.25,5.275)
  rect 1.194x2.743 smd: 76(-10.35,4.5) 77(10.35,4.5)
PHJK-2SJ3080-088111F-6P
  oval 0.991x1.905 hole 0.61x1.499: 1(-4.85,4.1) 2(4.7,-1.4) 3(-4.85,-3.7) 4(4.7,-4.3) 5(4.7,4.1) 6(4.7,1.35) 7(-4.85,0)
POWER-5X5-1_27-5P
  rect 1.143x0.762 smd: 1(2.875,-1.905) 2(2.875,-0.635) 3(2.875,0.635) 4(2.875,1.905)
  custom 1.14x1.14 smd: 5(0,0)
POWER-5X6-1_27-7P
  rect 0.635x0.66 smd: 1(2.835,-1.905) 5(-2.835,1.905) 6(-2.835,0.635) 7(-2.835,-0.635) 8(-2.835,-1.905)
  custom 0.485x0.485 smd: 2(2.18,0.115)
  rect 2.159x3.988 smd: 9(-0.525,0)
PVQFN20-3_5X3_5-5-25P
  rect 0.279x0.838 smd: 1(-1,-1.725) 2(-0.5,-1.725) 3(0,-1.725) 4(0.5,-1.725) 5(1,-1.725) 11(1,1.725) 12(0.5,1.725) 13(0,1.725) 14(-0.5,1.725) 15(-1,1.725)
  rect 0.838x0.279 smd: 6(1.725,-1) 7(1.725,-0.5) 8(1.725,0) 9(1.725,0.5) 10(1.725,1) 16(-1.725,1) 17(-1.725,0.5) 18(-1.725,0) 19(-1.725,-0.5) 20(-1.725,-1)
  rect 2.057x2.057 smd: 21(0,0)
  round 0.61 hole 0.305: 22(-0.5,-0.5) 23(0.5,-0.5) 24(0.5,0.5) 25(-0.5,0.5)
QFN14-3X3-4-16P
  rect 0.203x1.092 smd: 1(-0.525,-1.25) 2(0.175,-1.25) 8(0.525,1.25) 9(-0.175,1.25)
  rect 0.711x0.203 smd: 3(1.45,-0.8) 4(1.45,-0.4) 5(1.45,0) 6(1.45,0.4) 7(1.45,0.8) 10(-1.45,0.8) 11(-1.45,0.4) 12(-1.45,0) 13(-1.45,-0.4) 14(-1.45,-0.8)
  rect 0.203x0.66 smd: 15(-0.165,0) 16(0.435,0)
QFN24-4X4-5-25P-ALC5629
  rect 0.305x0.991 smd: 1(-1.25,-2.1) 2(-0.75,-2.1) 3(-0.25,-2.1) 4(0.25,-2.1) 5(0.75,-2.1) 6(1.25,-2.1) 13(1.25,2.1) 14(0.75,2.1) 15(0.25,2.1) 16(-0.25,2.1) 17(-0.75,2.1) 18(-1.25,2.1)
  rect 0.991x0.305 smd: 7(2.1,-1.25) 8(2.1,-0.75) 9(2.1,-0.25) 10(2.1,0.25) 11(2.1,0.75) 12(2.1,1.25) 19(-2.1,1.25) 20(-2.1,0.75) 21(-2.1,0.25) 22(-2.1,-0.25) 23(-2.1,-0.75) 24(-2.1,-1.25)
  rect 2.261x2.261 smd: 25(0,0)
QFN28-4X4-4-29P-RT5041A
  rect 0.203x0.991 smd: 1(-1.2,-2.1) 2(-0.8,-2.1) 3(-0.4,-2.1) 4(0,-2.1) 5(0.4,-2.1) 6(0.8,-2.1) 7(1.2,-2.1) 15(1.2,2.1) 16(0.8,2.1) 17(0.4,2.1) 18(0,2.1) 19(-0.4,2.1) 20(-0.8,2.1) 21(-1.2,2.1)
  rect 0.991x0.203 smd: 8(2.1,-1.2) 9(2.1,-0.8) 10(2.1,-0.4) 11(2.1,0) 12(2.1,0.4) 13(2.1,0.8) 14(2.1,1.2) 22(-2.1,1.2) 23(-2.1,0.8) 24(-2.1,0.4) 25(-2.1,0) 26(-2.1,-0.4) 27(-2.1,-0.8) 28(-2.1,-1.2)
  rect 2.388x2.388 smd: 29(0,0)
QFN28-5X5-5-29P-GL850G
  rect 0.305x0.991 smd: 1(-1.5,-2.6) 2(-1,-2.6) 3(-0.5,-2.6) 4(0,-2.6) 5(0.5,-2.6) 6(1,-2.6) 7(1.5,-2.6) 15(1.5,2.6) 16(1,2.6) 17(0.5,2.6) 18(0,2.6) 19(-0.5,2.6) 20(-1,2.6) 21(-1.5,2.6)
  rect 0.991x0.305 smd: 8(2.6,-1.5) 9(2.6,-1) 10(2.6,-0.5) 11(2.6,0) 12(2.6,0.5) 13(2.6,1) 14(2.6,1.5) 22(-2.6,1.5) 23(-2.6,1) 24(-2.6,0.5) 25(-2.6,0) 26(-2.6,-0.5) 27(-2.6,-1) 28(-2.6,-1.5)
  rect 3.505x3.505 smd: 29(0,0)
QFN32-4X4-4-33P-RT8171B
  rect 0.203x0.94 smd: 1(-1.4,-2.125) 2(-1,-2.125) 3(-0.6,-2.125) 4(-0.2,-2.125) 5(0.2,-2.125) 6(0.6,-2.125) 7(1,-2.125) 8(1.4,-2.125) 17(1.4,2.125) 18(1,2.125) 19(0.6,2.125) 20(0.2,2.125) 21(-0.2,2.125) 22(-0.6,2.125) 23(-1,2.125) 24(-1.4,2.125)
  rect 0.94x0.203 smd: 9(2.125,-1.4) 10(2.125,-1) 11(2.125,-0.6) 12(2.125,-0.2) 13(2.125,0.2) 14(2.125,0.6) 15(2.125,1) 16(2.125,1.4) 25(-2.125,1.4) 26(-2.125,1) 27(-2.125,0.6) 28(-2.125,0.2) 29(-2.125,-0.2) 30(-2.125,-0.6) 31(-2.125,-1) 32(-2.125,-1.4)
  rect 2.692x2.692 smd: 33(0,0)
QFN48-6X6-4-49P-ALC280
  rect 0.203x0.991 smd: 1(-2.2,-3.1) 2(-1.8,-3.1) 3(-1.4,-3.1) 4(-1,-3.1) 5(-0.6,-3.1) 6(-0.2,-3.1) 7(0.2,-3.1) 8(0.6,-3.1) 9(1,-3.1) 10(1.4,-3.1) 11(1.8,-3.1) 12(2.2,-3.1) 25(2.2,3.1) 26(1.8,3.1) 27(1.4,3.1) 28(1,3.1) 29(0.6,3.1) 30(0.2,3.1) 31(-0.2,3.1) 32(-0.6,3.1) 33(-1,3.1) 34(-1.4,3.1) 35(-1.8,3.1) 36(-2.2,3.1)
  rect 0.991x0.203 smd: 13(3.1,-2.2) 14(3.1,-1.8) 15(3.1,-1.4) 16(3.1,-1) 17(3.1,-0.6) 18(3.1,-0.2) 19(3.1,0.2) 20(3.1,0.6) 21(3.1,1) 22(3.1,1.4) 23(3.1,1.8) 24(3.1,2.2) 37(-3.1,2.2) 38(-3.1,1.8) 39(-3.1,1.4) 40(-3.1,1) 41(-3.1,0.6) 42(-3.1,0.2) 43(-3.1,-0.2) 44(-3.1,-0.6) 45(-3.1,-1) 46(-3.1,-1.4) 47(-3.1,-1.8) 48(-3.1,-2.2)
  rect 4.394x4.394 smd: 49(0,0)
R0402
  custom 0.12x0.12 smd: 1(0.39,0) 2(-0.39,0)
R0603
  rect 0.813x0.813 smd: 1(0.6,0) 2(-0.6,0)
R0805
  rect 0.864x1.372 smd: 1(0.88,0) 2(-0.88,0)
R1206
  rect 1.219x1.626 smd: 1(1.4,0) 2(-1.4,0)
RC3216
  rect 3.2x0.94 smd: 1(0,0.825) 2(0,-0.825)
S0402
  custom 0.125x0.125 smd: 1(0.39,0) 2(-0.39,0)
S0603
  rect 1.041x0.813 smd: 1(0.6,0) 2(-0.6,0)
S0805
  rect 1.346x1.372 smd: 1(0.88,0) 2(-0.88,0)
SATA-C166FQ-12208-L-22P-R
  round 1.067 hole 0.711: 1(15.875,-0.8) 2(14.605,-0.8) 3(13.335,-0.8) 4(12.065,-0.8) 5(10.795,-0.8) 6(9.525,-0.8) 7(8.255,-0.8) 8(1.905,-0.8) 9(0.635,-0.8) 10(-0.635,-0.8) 11(-1.905,-0.8) 12(-3.175,-0.8) 13(-4.445,-0.8) 14(-5.715,-0.8) 15(-6.985,-0.8) 16(-8.255,-0.8) 17(-9.525,-0.8) 18(-10.795,-0.8) 19(-12.065,-0.8) 20(-13.335,-0.8) 21(-14.605,-0.8) 22(-15.875,-0.8)
  oval 1.803x2.87 hole 0.991x2.083: 23(18.71,0) 24(-18.71,0)
SC70-2_1-65-6P
  rect 1.27x0.279 smd: 1(1.02,-0.65) 2(1.02,0) 3(1.02,0.65) 4(-1.02,0.65) 5(-1.02,0) 6(-1.02,-0.65)
SC70-2_1-65-6P-0_95H
  rect 0.508x0.406 smd: 1(0.95,-0.65) 2(0.95,0) 3(0.95,0.65) 4(-0.95,0.65) 5(-0.95,0) 6(-0.95,-0.65)
SDCARD-156-2001902600-11P-SMT
  round 1.194 hole 1.194 unplated: (-11.95,0)
  round 0.787 hole 0.787 unplated: (11.9,0)
  rect 0.787x1.803 smd: 1(-10.875,1.46) 2(-9.375,1.46) 3(-6.875,1.46) 4(-4.375,1.46) 5(-1.875,1.46) 6(0.625,1.46) 7(3.125,1.46) 8(5.625,1.46) 9(7.545,1.46) 10(9.245,1.46) 11(10.945,1.46)
  oval 0.94x2.134 hole 0.61x1.168: 12(12.175,-11.2) 13(-12.175,-11.2)
  oval 1.092x2.134 hole 0.61x1.168: 14(12.35,-2.9) 15(-12.35,-2.9)
SENSOR-1_3X0_9-5-4P
  rect 0.457x0.254 smd: 1(-0.625,0.25) 2(-0.625,-0.25) 3(0.625,-0.25) 4(0.625,0.25)
SHORT3720
  rect 3.759x1.537 smd: 1(0,1.008) 2(0,-1.008)
SO-8FL-5P-OA
  rect 0.991x0.762 smd: 1(3.73,-1.905) 2(3.73,-0.635) 3(3.73,0.635) 4(3.73,1.905)
  custom 1.132x1.132 smd: 5(0,0)
SOIC8-6-1_27
  rect 0.533x1.753 smd: 1(-1.905,-2.73) 2(-0.635,-2.73) 3(0.635,-2.73) 4(1.905,-2.73) 5(1.905,2.73) 6(0.635,2.73) 7(-0.635,2.73) 8(-1.905,2.73)
SOIC8-7_9-1_27
  rect 0.533x1.549 smd: 1(-1.905,-3.775) 2(-0.635,-3.775) 3(0.635,-3.775) 4(1.905,-3.775) 5(1.905,3.775) 6(0.635,3.775) 7(-0.635,3.775) 8(-1.905,3.775)
SOT23-2_8-95-6P
  rect 1.346x0.508 smd: 1(1.325,-0.95) 2(1.325,0) 3(1.325,0.95) 4(-1.325,0.95) 5(-1.325,0) 6(-1.325,-0.95)
SOT23-5
  rect 1.016x0.711 smd: 1(1.2,-0.95) 2(1.2,0) 3(1.2,0.95) 4(-1.2,0.95) 5(-1.2,-0.95)
SOT23-5-2_8-95-5P-1_3H
  rect 1.194x0.533 smd: 1(1.5,-0.95) 2(1.5,0) 3(1.5,0.95) 4(-1.5,0.95) 5(-1.5,-0.95)
SOT23_123-2_8-1_9
  rect 1.092x0.533 smd: 1(1.45,-0.95) 2(1.45,0.95) 3(-1.45,0)
SOT23_213-3_3-2
  rect 1.27x1.016 smd: 1(1.016,1.016) 2(1.016,-1.016) 3(-1.016,0)
SOT323_213-2_1-1_3-2N7002W
  rect 0.787x0.61 smd: 1(0.8,0.65) 2(0.8,-0.65) 3(-0.8,0)
SPAD-C315
  round 8.001 smd: 1(0,0)
SPAD-S354NP
  rect 8.992x8.992 smd: 1(0,0)
SPAD-ZHX-2
  custom 1.15x1.15 smd: 1(0,0)
SPAD-ZXX-5
  custom 3.25x3.25 smd: 1(0,0)
SW-DS-A40E-4P
  round 1.041 hole 1.041 unplated: (0,-1.5)
  oval 0.838x0.94 hole 0.838x0.94 unplated: (0,1)
  rect 0.787x1.194 smd: 1(-2.15,-1.2) 2(-2.15,1.2) 3(2.15,-1.2) 4(2.15,1.2)
SW-NTC031-AB1G-A160T-4P
  rect 1.092x1.092 smd: 1(-1.85,3.05) 2(1.85,3.05) 3(-1.85,-3.05) 4(1.85,-3.05)
  rect 0.559x0.991 smd: 5(-2.575,0) 6(2.575,0)
TP2650
  round 0.66 smd: 1(0,0)
TP2675
  round 0.66 smd: 1(0,0)
TQFN20-3X3-4-21P
  rect 0.203x0.711 smd: 1(-0.8,-1.5) 2(-0.4,-1.5) 3(0,-1.5) 4(0.4,-1.5) 5(0.8,-1.5) 11(0.8,1.5) 12(0.4,1.5) 13(0,1.5) 14(-0.4,1.5) 15(-0.8,1.5)
  rect 0.711x0.203 smd: 6(1.5,-0.8) 7(1.5,-0.4) 8(1.5,0) 9(1.5,0.4) 10(1.5,0.8) 16(-1.5,0.8) 17(-1.5,0.4) 18(-1.5,0) 19(-1.5,-0.4) 20(-1.5,-0.8)
  rect 1.499x1.499 smd: 21(0,0)
TSSOP28-6_4-65-SLB9635TT
  rect 0.406x1.295 smd: 1(-4.225,-3.05) 2(-3.575,-3.05) 3(-2.925,-3.05) 4(-2.275,-3.05) 5(-1.625,-3.05) 6(-0.975,-3.05) 7(-0.325,-3.05) 8(0.325,-3.05) 9(0.975,-3.05) 10(1.625,-3.05) 11(2.275,-3.05) 12(2.925,-3.05) 13(3.575,-3.05) 14(4.225,-3.05) 15(4.225,3.05) 16(3.575,3.05) 17(2.925,3.05) 18(2.275,3.05) 19(1.625,3.05) 20(0.975,3.05) 21(0.325,3.05) 22(-0.325,3.05) 23(-0.975,3.05) 24(-1.625,3.05) 25(-2.275,3.05) 26(-2.925,3.05) 27(-3.575,3.05) 28(-4.225,3.05)
UMT_213-3-1_3
  rect 1.016x0.762 smd: 1(0.991,0.66) 2(0.991,-0.66) 3(-0.991,0)
unnamed#2
  round 1.016 smd: 1(0,0)
USB-53065-00902-001-9P-SMT
  round 1.295 hole 0.813: 1(3.5,8.7) 2(1,8.7) 3(-1,8.7) 4(-3.5,8.7) 5(-4,7.2) 6(-2,7.2) 7(0,7.2) 8(2,7.2) 9(4,7.2)
  oval 1.397x2.388 hole 0.787x1.803: 10(6.4,7.8) 11(-6.4,7.8)
  oval 1.397x3.2 hole 0.787x2.591: 12(-7.85,0) 13(7.85,0)
VSSOP8-3_1-5-8P
  rect 0.203x1.168 smd: 1(-0.75,-1.563) 2(-0.25,-1.563) 3(0.25,-1.563) 4(0.75,-1.563) 5(0.75,1.563) 6(0.25,1.563) 7(-0.25,1.563) 8(-0.75,1.563)
WDFN5-3_05X3_05-65
  rect 0.66x0.432 smd: 1(1.385,-0.975) 2(1.385,-0.325) 3(1.385,0.325) 4(1.385,0.975)
  custom 0.575x0.575 smd: 5(-0.735,0)
XTL-3_2X1_5-2_5-0_8H
  rect 0.991x1.803 smd: 1(-1.25,0) 2(1.25,0)
XTL-3_2X2_5-2_2X1_7
  rect 1.397x1.194 smd: 1(-1.1,-0.85) 2(1.1,-0.85) 3(1.1,0.85) 4(-1.1,0.85)
XTL-3_2X2_5-2_2X1_8-4P
  rect 1.397x1.194 smd: 1(-1.1,-0.9) 2(1.1,-0.9) 3(1.1,0.9) 4(-1.1,0.9)

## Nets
2.469V: PR13.1 PR14.2 PU2.3
5V_HSMBCK: D14.1 R269.1
5V_HSMBDT: D13.1 R268.1
5VUSB_0: C1.2 C2.2 C14.2 CN1.1 U36.1
5VUSB_1: C3.1 C16.2 CN3.1 CN3.2 CN3.3 CN3.4 U1.1
51216VBST: PR120.2 PU7.15
51216VBST_S: PC105.1 PR120.1
51216VDDQSNS: PR132.2 PU7.9
+1.5V: C35.1 C38.1 L7.2 PC19.1 PU1.10 Q11.2 R125.2 R402.1 U4.9
+1.05V_S5: C143.2 C144.2 C145.2 C146.2 C147.2 C148.2 C182.2 C188.2 C205.2 C206.1 C207.2 C214.1 C216.1 C220.2 JP2.2 PC9.1 PC147.2 PC156.2 PR62.1 PR79.2 PR171.1 PR187.1 PR188.2 PR197.1 R138.1 R142.1 R147.2 R319.1 R323.2 R324.2 R325.2 R326.2 R365.1 R377.1 R381.2 R425.2 R426.2 U7.AA18 U7.AA19 U7.AA21 U7.AA22 U7.AA24 U7.AA25 U7.AC18 U7.AC19 U7.AC21 U7.AC22 U7.AC24 U7.AC25 U7.AD25 U7.AD27
+1.5VA: C65.1 C69.1 C880.1 L7.1 U4.40
+1.8V: PQ2.1 PR139.1 Q1.2 Q1.5 Q15.2 Q17.2 Q22.2 Q53.2 R6.1 R7.1 R19.2 R170.1 R201.1 R227.1 R401.1 R490.1 R500.1 R503.1 R671.2 R1028.1 R1127.1 R1200.1 U11.1
+1.8V_EMMC: C322.2 C327.2 C328.1 C331.2 C334.1 R503.2 U20.C6 U20.M4 U20.N4 U20.P3 U20.P5
+1.8V_LDO_EC: C859.1 R1179.1 U37.5
+1.8V_S5: C59.2 C258.2 C319.2 JP3.2 PC14.1 PC21.1 PC22.1 PC23.1 PQ2.3 PR128.2 PR172.1 PR204.1 PU1.7 PU1.8 PU1.9 PU1.14 Q32.2 Q33.2 Q34.2 Q36.2 Q36.5 Q39.2 R23.2 R30.2 R33.1 R34.1 R35.1 R36.1 R37.1 R39.2 R40.1 R46.2 R48.2 R56.2 R57.1 R59.1 R64.2 R76.1 R77.1 R80.2 R81.1 R92.1 R97.2 R98.2 R99.2 R101.2 R102.1 R111.2 R115.2 R117.2 R122.2 R127.2 R132.2 R150.2 R151.2 R154.2 R155.2 R156.2 R157.2 R158.2 R165.1 R171.2 R172.1 R173.1 R176.1 R180.2 R186.2 R189.2 R193.2 R194.2 R196.1 R198.2 R221.2 R223.1 R224.1 R225.1 R226.1 R232.2 R278.2 R305.1 R307.1 R320.1 R322.2 R329.1 R353.2 R356.2 R357.2 R358.2 R359.2 R364.2 R398.1 R418.1 R419.1 R423.2 R424.2 R427.2 R428.1 R498.2 R499.2 R1008.2 R1009.2 R1010.2 R1026.1 R1128.2 R1129.2 R1180.1 R1182.1 R1184.1 R1186.1 R1199.2 U5.8 U15.2 U16.1 U19.2
+1.8VREF: PC90.1 PR111.1 PU7.6
+1.15V: PC120.1 PU1.6 R414.2 R417.2 R444.2
+1.24VS5: PC121.1 PU1.5 R312.2 R313.1 R314.2 R315.2 R316.2 R334.2 R338.2 R347.2 R354.2 R395.1
+1.35VSUS: C18.2 C19.2 C257.2 C265.2 C266.2 C267.2 C703.1 C711.1 C712.1 C713.1 C714.1 C715.1 C716.1 C717.1 C718.1 C720.2 C721.2 C722.2 C723.2 C724.2 C725.1 C726.1 C728.1 C729.1 C730.1 C731.1 C736.1 C737.1 C738.1 C739.1 C740.1 C741.1 C742.1 C743.1 C744.1 C751.1 C752.1 C753.1 C754.1 C755.1 C756.1 C757.1 C758.1 C759.1 C760.1 C761.1 C762.1 C763.2 C767.2 C768.2 C769.1 C770.2 C771.2 C772.2 C785.1 C786.1 C787.1 C788.1 C789.1 C790.1 C791.1 C792.1 C869.2 C870.2 C871.2 C872.2 JP8.2 PC82.1 PU7.2 R436.2 R437.2 R457.2 R465.2 R1040.1 R1042.1 R1108.1 U7.AM18 U7.AM36 U7.AN18 U7.AN19 U7.AN35 U7.AN36 U7.AU18 U7.AU36 U7.AV10 U7.AV16 U7.AV38 U7.AV44 U7.AY10 U7.AY44 U7.BE1 U7.BE3 U7.BE51 U7.BE53 U7.BG3 U7.BG51 U7.BH4 U7.BH5 U7.BH49 U7.BH50 U7.BJ2 U7.BJ3 U7.BJ5 U7.BJ49 U7.BJ51 U7.BJ52 U24.A1 U24.A8 U24.B2 U24.C1 U24.C9 U24.D2 U24.D9 U24.E9 U24.F1 U24.G7 U24.H2 U24.H9 U24.K2 U24.K8 U24.N1 U24.N9 U24.R1 U24.R9 U25.A1 U25.A8 U25.B2 U25.C1 U25.C9 U25.D2 U25.D9 U25.E9 U25.F1 U25.G7 U25.H2 U25.H9 U25.K2 U25.K8 U25.N1 U25.N9 U25.R1 U25.R9 U26.A1 U26.A8 U26.B2 U26.C1 U26.C9 U26.D2 U26.D9 U26.E9 U26.F1 U26.G7 U26.H2 U26.H9 U26.K2 U26.K8 U26.N1 U26.N9 U26.R1 U26.R9 U27.A1 U27.A8 U27.B2 U27.C1 U27.C9 U27.D2 U27.D9 U27.E9 U27.F1 U27.G7 U27.H2 U27.H9 U27.K2 U27.K8 U27.N1 U27.N9 U27.R1 U27.R9 U31.A1 U31.A8 U31.B2 U31.C1 U31.C9 U31.D2 U31.D9 U31.E9 U31.F1 U31.G7 U31.H2 U31.H9 U31.K2 U31.K8 U31.N1 U31.N9 U31.R1 U31.R9 U32.A1 U32.A8 U32.B2 U32.C1 U32.C9 U32.D2 U32.D9 U32.E9 U32.F1 U32.G7 U32.H2 U32.H9 U32.K2 U32.K8 U32.N1 U32.N9 U32.R1 U32.R9 U33.A1 U33.A8 U33.B2 U33.C1 U33.C9 U33.D2 U33.D9 U33.E9 U33.F1 U33.G7 U33.H2 U33.H9 U33.K2 U33.K8 U33.N1 U33.N9 U33.R1 U33.R9 U34.A1 U34.A8 U34.B2 U34.C1 U34.C9 U34.D2 U34.D9 U34.E9 U34.F1 U34.G7 U34.H2 U34.H9 U34.K2 U34.K8 U34.N1 U34.N9 U34.R1 U34.R9
+3V: C53.1 C56.1 C58.1 C90.1 C101.1 C861.1 C865.2 C874.1 C876.1 PQ4.1 PQ4.2 PQ4.3 PR52.2 PR58.2 PR104.2 PR138.1 PR238.1 Q19.2 Q43.2 Q77.1 R41.1 R105.1 R108.1 R114.1 R129.2 R135.1 R182.2 R197.2 R199.2 R215.2 R216.2 R252.2 R279.2 R282.2 R289.1 R300.2 R301.2 R306.1 R337.1 R416.2 R429.2 R432.1 R433.1 R434.1 R459.1 R481.2 R504.2 R517.1 R781.1 R1005.2 R1022.1 R1031.1 R1116.2 R1126.1 R1144.1 R1172.2 R1173.2 R1189.1 R1194.2 R1205.1 R1206.1 U4.1 U4.36 U8.1 U12.4 U12.6 U38.8
+3V3_SER: C840.1 C841.1 Q54.3 R486.1 R781.2
+3V_EC: C287.1 R459.2 R1030.2 U9.11
+3V_EMMC: C336.1 C337.1 C338.2 C339.2 C340.2 R517.2 U20.E6 U20.F5 U20.J10 U20.K9
+3V_LDO: C860.1 PC33.2 PR157.2 PU3.6 R1177.1 U37.1
+3V_MINI1_VDD: C41.2 C132.2 C133.2 C171.1 CN5.2 CN5.4 CN5.72 CN5.74 Q25.2 Q27.3 R331.2 R337.2 R598.1
+3V_RTC: C294.1 D17.3 R38.1 R58.1 R259.1 R318.1 R998.1 R1037.1
+3V_RTC_0: CN7.1 Q31.1 R479.2
+3V_RTC_R: C279.1 R446.2 R454.2 R1157.2 U9.106
+3V_S5: PC114.1 PU1.18 Q54.1 R49.2 R149.1 R220.2 R231.1 R299.1 R309.1 R328.1 R430.1 R441.2 R463.1 R470.1 R491.2 R507.1 R782.2 R1023.2 R1024.2 R1030.1 R1113.1 U16.6 U18.5
+3V_SRC: JP5.1 PC26.1 PC27.1 PC28.1 PC30.1 PC31.1 PC35.1 PL3.2 PR146.1 PU3.7
+3V_SSD: C601.1 C602.1 C862.1 C863.1 CN9.8 CN9.9 R1005.1 R1020.2 R1150.2
+3V_USB: C798.2 C799.2 C800.2 C801.2 C802.2 C803.2 C804.2 C805.2 C867.2 R1113.2 R1114.2 R1115.2 R1116.1 R1117.2 R1118.2 R1119.2 R1122.2 R1123.2 U35.5 U35.9 U35.14 U35.28
+3V_USB_D: R1122.1 U35.21
+3VPCU: C75.1 C576.2 D17.2 JP1.2 JP5.2 LED2.3 MR3.3 PC116.1 PC164.1 PQ4.5 PQ32.3 PR6.1 PR91.2 PR92.2 PR123.2 PR125.2 PR156.1 PR221.2 PR223.2 PR228.2 PU1.17 Q27.1 R17.2 R79.2 R107.2 R235.2 R248.2 R257.1 R281.1 R293.1 R303.1 R310.1 R376.1 R435.2 R990.2 R991.2 R1014.1 R1178.1 R1207.1 RP1.5 RP1.10
+3VPCU_EC: C124.1 C282.1 C283.1 C288.1 C289.1 C297.1 L9.2 L11.1 R454.1 R460.2 R1161.1 U9.26 U9.50 U9.92 U9.121
+3VPCU_EC_MAIN: R212.2 R213.2 R214.2 R440.1 R460.1 R1175.2 R1177.2 R1178.2
+3VPCU_ECPLL: C104.1 L9.1 U9.127
+3VSUS: PQ32.1 PR183.1 R501.1
+5V: C81.1 C83.1 C868.2 C875.1 D13.2 D14.2 L4.1 L8.1 PQ29.1 PQ29.2 PQ29.3 PR137.1 Q14.3 R130.2 R450.2
+5V_HDD: C108.1 C270.1 C272.1 C274.1 C278.1 CN9.14 CN9.15 CN9.16 R450.1
+5V_S5: C15.2 C842.2 C866.1 PC107.1 PQ17.1 PQ17.2 PQ17.3 PR45.1 PR53.1 PR57.1 PR75.1 PR108.1 PR153.1 PR166.1 PR170.1 PR177.2 PR185.2 PR194.1 PU7.12 R407.1 R410.1 U1.5 U36.5
+5VA: C31.1 C32.1 C879.1 L4.2 U4.26
+5VPCU: JP11.2 PC124.1 PC125.1 PC126.1 PQ17.5 PQ29.5 PR9.1 PU1.1 PU1.2
+15V: PR143.1 PR162.1 PR178.1 PR201.1
+A3VPCU: C118.1 L11.2 U9.74
+PVCC_VGG: PC152.2 PR57.2 PU6.21
+VCC_CORE: C221.2 C222.2 C223.2 C235.2 C236.2 C237.2 C238.2 C239.2 C241.2 C242.2 C864.2 PC25.1 PC29.1 PC39.1 PC44.1 PL4.2 PR147.2 U7.AF29 U7.AF30 U7.AF36 U7.AG27 U7.AG29 U7.AG30 U7.AG33 U7.AG35 U7.AG36 U7.AG38 U7.AJ27 U7.AJ29 U7.AJ30 U7.AJ33 U7.AJ36 U7.AJ38
+VCC_VGG: PC161.2 PR87.1 PR108.2 PU6.6
+VDDQ_VTT: PC86.1 PU7.1 PU7.3 R1043.1
+VDDQ_VTT_M0_M1_R: C12.1 C13.1 C48.1 C704.1 C705.1 C706.1 C707.1 C708.1 C709.1 C710.1 C749.1 C777.1 C778.1 C779.1 C780.1 C781.1 C782.1 C783.1 C784.1 C793.1 C872.1 R1043.2 R1049.1 R1050.1 R1051.1 R1052.1 R1053.1 R1054.1 R1055.1 R1056.1 R1057.1 R1058.1 R1059.1 R1060.1 R1061.1 R1062.1 R1063.1 R1064.1 R1065.1 R1066.1 R1067.1 R1068.1 R1069.1 R1070.1 R1071.1 R1072.1 R1073.1 R1079.1 R1080.1 R1081.1 R1082.1 R1083.1 R1084.1 R1085.1 R1086.1 R1087.1 R1088.1 R1089.1 R1090.1 R1091.1 R1092.1 R1093.1 R1094.1 R1095.1 R1096.1 R1097.1 R1098.1 R1099.1 R1100.1 R1101.1 R1102.1 R1103.1
+VIN: C866.2 C877.1 C878.1 JP7.2 JP10.2 JP12.2 PC63.1 PC65.1 PC94.1 PC95.2 PC106.1 PC111.2 PC112.1 PC122.1 PC123.2 PC149.1 PC151.1 PC169.1 PC170.2 PC172.1 PD1.2 PQ6.2 PQ9.5 PQ10.1 PQ10.2 PQ10.3 PQ13.5 PR136.2 PR140.2 PR144.1 PR167.1 PR186.1 PR190.1 PR191.1 PR217.1 PR218.1 PR229.1 R405.1 R406.1
+VIN_VCORE: JP12.1 PC64.1 PC66.1 PC75.1 PC148.1 PC150.1 PQ7.2 PR51.1
DVDD: C425.1 C426.1 C427.1 Q77.3 R1144.2 U23.4
